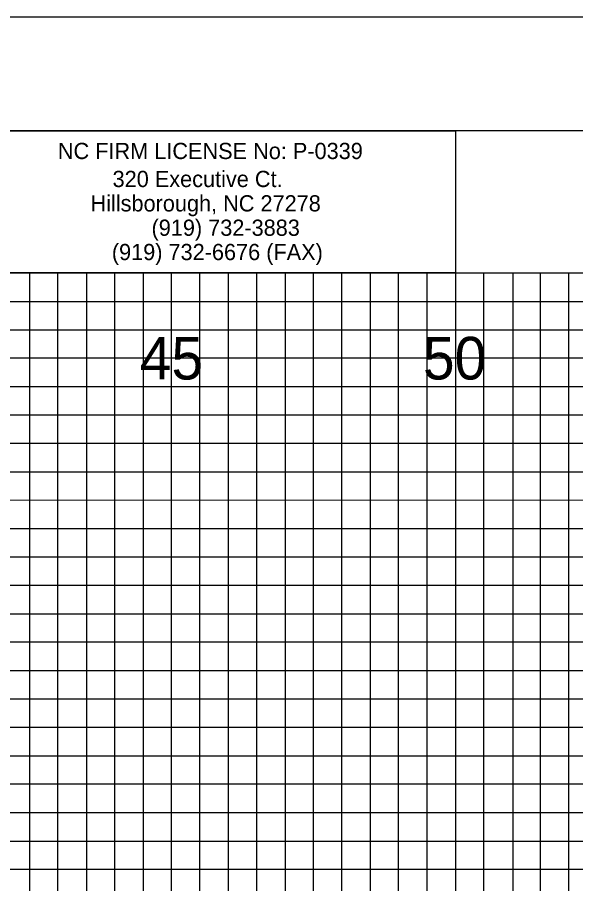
# Model space of a CAD drawing. Extents: x -7 to 162, y -2 to 217.
# Drawn here: x 122.28 to 132.12, y 91.75 to 107 of the extents above; entities that cross this region are included whole.
import ezdxf

# ---------------------------------------------------------------- set-up
doc = ezdxf.new("R2010")
doc.units = 0
for name, color, linetype in [('Exist Cross Section Cell', 7, 'Continuous'), ('Prop CMT Pvmt Course 2', 7, 'Continuous'), ('Prop CMT Pvmt Course 2 Wedge', 7, 'Continuous'), ('Prop CMT Pvmt Course 3', 7, 'Continuous'), ('Prop CMT Pvmt Surface', 7, 'Continuous'), ('Prop CMT Shld Paved Course 1', 7, 'Continuous'), ('Prop CMT Shld Paved Course 2', 7, 'Continuous'), ('Prop CMT Shld Paved Course 3', 7, 'Continuous'), ('Prop CMT Subgrade Earthwork', 7, 'Continuous'), ('Scratch_Level_3', 7, 'Continuous')]:
    doc.layers.add(name, color=color, linetype=linetype)

msp = doc.modelspace()

# ---------------------------------------------------------------- linework, layer by layer
at = {"layer": 'Prop CMT Pvmt Course 2'}
for p, q in [((130, 104.5), (130, 103.99)), ((130, 103.5), (130, 102.945)), ((0, 102), (160, 102))]:
    msp.add_line(p, q, dxfattribs=at)
for points in [[(0, 101.5), (135, 101.5), (160, 101.5)], [(160, 101), (0, 101)], [(0, 100.5), (160, 100.5)], [(160, 99.5), (0, 99.5)], [(0, 99), (160, 99)], [(160, 98.5), (0, 98.49)], [(0, 98), (160, 98)], [(160, 97), (0, 97)], [(0, 96.5), (160, 96.5), (160, 96), (0, 96)], [(0, 95.5), (160, 95.5), (160, 94.5), (0, 94.5)], [(0, 94), (160, 94), (160, 93.5), (0, 93.5)], [(0, 93), (160, 93), (160, 92), (0, 92)]]:
    msp.add_lwpolyline(points, dxfattribs=at)
at = {"layer": 'Prop CMT Pvmt Course 3'}
for p, q in [((125, 105), (120, 105)), ((130, 105), (130, 0)), ((125, 0), (125, 102.5))]:
    msp.add_line(p, q, dxfattribs=at)
for points in [[(160, 102.5), (160, 95), (0, 95)], [(0, 100), (160, 100)]]:
    msp.add_lwpolyline(points, dxfattribs=at)
at = {"layer": 'Prop CMT Pvmt Surface'}
msp.add_lwpolyline([(110.951, 105), (130, 105), (130, 102.5), (110.951, 102.5)], close=True, dxfattribs=at)
at = {"layer": 'Prop CMT Shld Paved Course 1'}
msp.add_lwpolyline([(-6.7, -2.5), (161.65, -2.5), (161.65, 107), (-6.7, 107)], close=True, dxfattribs=at)
at = {"layer": 'Prop CMT Shld Paved Course 2'}
msp.add_lwpolyline([(-5.4, -0.5), (161.2, -0.5), (161.2, 105), (-5.4, 105)], close=True, dxfattribs=at)
at = {"layer": 'Prop CMT Shld Paved Course 3'}
for points in [[(117.5, 105), (122.5, 105)], [(127.5, 105), (129.965, 105), (130, 105), (130, 102.5), (132.495, 102.5), (132.495, 0), (137.5, 0), (137.5, 102.5), (140, 102.5)], [(0, 102.5), (137.5, 102.5)], [(0, 92.5), (160, 92.5), (160, 102.5)], [(122.5, 102.5), (122.5, 0), (127.5, 0), (127.5, 102.5)], [(160, 97.5), (0, 97.5)]]:
    msp.add_lwpolyline(points, dxfattribs=at)
at = {"layer": 'Prop CMT Subgrade Earthwork'}
for points in [[(123, 105), (123.5, 105)], [(124, 105), (124.5, 105)], [(125.5, 105), (126, 105)], [(126.5, 105), (127, 105)], [(128, 105), (128.5, 105)], [(129, 105), (129.5, 105)], [(122.5, 0), (123, 0), (123, 102.5)], [(123.5, 102.5), (123.5, 0)], [(123.5, 0), (124, 0), (124, 102.5)], [(124.5, 102.5), (124.5, 0)], [(125, 0), (125.5, 0), (125.5, 102.5)], [(126, 102.5), (126, 0)], [(126, 0), (126.5, 0), (126.5, 102.5)], [(127, 102.5), (127, 0)], [(127.5, 0), (128, 0), (128, 102.5)], [(128.5, 102.5), (128.5, 0)], [(128.5, 0), (129, 0), (129, 102.5)], [(129.5, 102.5), (129.5, 0)], [(130, 0), (130.5, 0), (130.5, 102.5), (131.01, 102.5), (131.01, 0)], [(131, 0), (131.5, 0), (131.5, 102.5), (131.995, 102.5), (131.995, 0)]]:
    msp.add_lwpolyline(points, dxfattribs=at)
at = {"layer": 'Scratch_Level_3'}
for points in [[(160, 105), (0, 105), (0, 0), (160, 0)], [(140, 105), (130, 105), (130, 102.5), (140, 102.5)]]:
    msp.add_lwpolyline(points, close=True, dxfattribs=at)

# ---------------------------------------------------------------- texts
at = {"layer": 'Exist Cross Section Cell'}
for s, p in [('45', (124.441, 100.625)), ('50', (129.429, 100.625))]:
    msp.add_text(s, height=0.75, dxfattribs=at).set_placement(p)
at = {"layer": 'Prop CMT Pvmt Course 2 Wedge'}
for s, p in [('NC FIRM LICENSE No: P-0339', (122.998, 104.505)), ('320 Executive Ct.', (123.962, 104.012)), ('Hillsborough, NC 27278', (123.573, 103.583)), ('(919) 732-3883', (124.648, 103.154)), ('(919) 732-6676 (FAX)', (123.949, 102.726))]:
    msp.add_text(s, height=0.28573, rotation=360, dxfattribs=at).set_placement(p)

doc.saveas('drawing.dxf')
